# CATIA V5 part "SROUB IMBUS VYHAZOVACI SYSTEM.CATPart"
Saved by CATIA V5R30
Part number: SROUB IMBUS VYHAZOVACI SYSTEM
Bounding box of the stored display mesh (mm): x -10 to 25, y -8 to 8, z -8 to 8
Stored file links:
  C:\Users\ondra\Desktop\PŘÍLOHA P III\CATIA\SROUB IMBUS VYHAZOVACI SYSTEM.CATPart
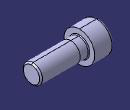
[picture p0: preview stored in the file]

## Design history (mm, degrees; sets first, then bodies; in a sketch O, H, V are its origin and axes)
Set1
  DatumSurface1 to DatumSurface30 "Z31/10x2"
  Join1: Elements (DatumSurface1; DatumSurface2; DatumSurface3; DatumSurface4; DatumSurface5; DatumSurface6; DatumSurface7; DatumSurface8; DatumSurface9; DatumSurface10; DatumSurface11; DatumSurface12; DatumSurface13; DatumSurface14; DatumSurface16; DatumSurface17; DatumSurface18; DatumSurface19; DatumSurface20; DatumSurface21; DatumSurface22; DatumSurface23; DatumSurface24; DatumSurface25; DatumSurface26; DatumSurface27; DatumSurface28; DatumSurface29; DatumSurface30)
Body1 (main body)
  CloseSurface1: CloseElement Join1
